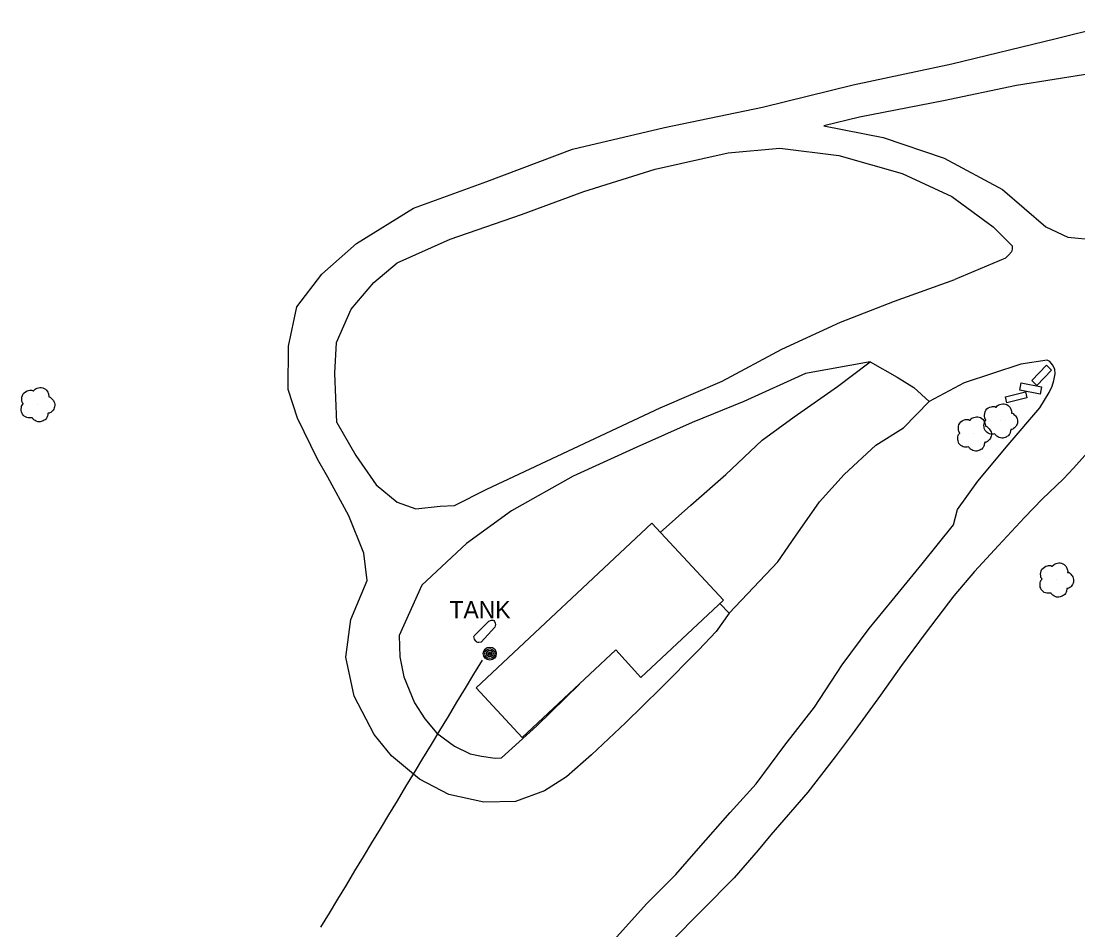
# Model space of a CAD drawing. Extents: x 368532 to 392481, y 10654822 to 10676899.
# Drawn here: x 370919.5 to 371228.1, y 10674746.6 to 10675012 of the extents above; entities that cross this region are included whole.
import ezdxf

# ---------------------------------------------------------------- set-up
doc = ezdxf.new("R2010")
doc.units = 0
for name, color, linetype in [('p_Catenary', 7, 'Continuous'), ('p_road conc barrier', 7, 'Continuous'), ('p_road dirt road', 7, 'Continuous'), ('p_road general road feature', 7, 'Continuous'), ('p_structure building', 7, 'Continuous'), ('p_structure tank', 7, 'Continuous'), ('p_utility general pole', 7, 'Continuous'), ('p_veg tree', 7, 'Continuous')]:
    doc.layers.add(name, color=color, linetype=linetype)

msp = doc.modelspace()

# ---------------------------------------------------------------- linework, layer by layer
at = {"layer": 'p_Catenary'}
msp.add_lwpolyline([(371007.04, 10674747.35), (371009.52, 10674751.46), (371012, 10674755.57), (371014.48, 10674759.67), (371016.96, 10674763.78), (371019.45, 10674767.89), (371021.93, 10674771.99), (371024.41, 10674776.1), (371026.89, 10674780.21), (371029.37, 10674784.31), (371031.86, 10674788.42), (371034.34, 10674792.52), (371036.82, 10674796.63), (371039.3, 10674800.74), (371041.78, 10674804.84), (371044.27, 10674808.95), (371046.75, 10674813.06), (371049.23, 10674817.16), (371051.71, 10674821.27), (371054.19, 10674825.37)], dxfattribs=at)
at = {"layer": 'p_road conc barrier'}
for p, q in [((371214.61, 10674907.02), (371218.96, 10674911.52)), ((371220.45, 10674910.08), (371216.1, 10674905.58)), ((371218.96, 10674911.52), (371220.45, 10674910.08)), ((371216.1, 10674905.58), (371214.61, 10674907.02)), ((371206.92, 10674902.29), (371212.78, 10674903.76)), ((371211.11, 10674904.21), (371211.53, 10674906.37)), ((371217.1, 10674903.05), (371211.11, 10674904.21)), ((371211.53, 10674906.37), (371217.52, 10674905.21)), ((371212.78, 10674903.76), (371213.21, 10674902.04)), ((371217.52, 10674905.21), (371217.1, 10674903.05)), ((371207.36, 10674900.57), (371206.92, 10674902.29)), ((371213.21, 10674902.04), (371207.36, 10674900.57))]:
    msp.add_line(p, q, dxfattribs=at)
at = {"layer": 'p_road dirt road'}
for p, q in [((371221.8, 10675006.97), (371241.96, 10675012.03)), ((371191.34, 10674999.54), (371221.8, 10675006.97)), ((371162.5, 10674993.47), (371191.34, 10674999.54)), ((371232.15, 10674996.7), (371210.22, 10674993.27)), ((371136.01, 10674986.9), (371162.5, 10674993.47)), ((371210.22, 10674993.27), (371188.87, 10674988.75)), ((371107.41, 10674980.93), (371136.01, 10674986.9)), ((371188.87, 10674988.75), (371164.34, 10674983.94)), ((371164.34, 10674983.94), (371153.88, 10674981.48)), ((371080.49, 10674974.59), (371107.41, 10674980.93)), ((371153.88, 10674981.48), (371171.26, 10674978.03)), ((371171.26, 10674978.03), (371189.09, 10674971.99)), ((371055.53, 10674965.22), (371080.49, 10674974.59)), ((371125.94, 10674973.54), (371141.1, 10674974.88)), ((371141.1, 10674974.88), (371158.3, 10674972.81)), ((371104.63, 10674968.75), (371125.94, 10674973.54)), ((371158.3, 10674972.81), (371176.76, 10674967.48)), ((371189.09, 10674971.99), (371206.11, 10674962.82)), ((371083.78, 10674962.31), (371104.63, 10674968.75)), ((371034.06, 10674957.4), (371055.53, 10674965.22)), ((371176.76, 10674967.48), (371191.26, 10674960.78)), ((371065.64, 10674955.56), (371083.78, 10674962.31)), ((371206.11, 10674962.82), (371218.78, 10674951.94)), ((371191.26, 10674960.78), (371203.41, 10674951.94)), ((371017.44, 10674947.07), (371034.06, 10674957.4)), ((371044.73, 10674948.31), (371065.64, 10674955.56)), ((371203.41, 10674951.94), (371208.88, 10674946.36)), ((371218.78, 10674951.94), (371225.14, 10674948.88)), ((371007.32, 10674938.11), (371017.44, 10674947.07)), ((371029.34, 10674941.46), (371044.73, 10674948.31)), ((371225.14, 10674948.88), (371233.23, 10674948.16)), ((371207.93, 10674943.75), (371206.97, 10674942.82)), ((371208.7, 10674944.61), (371207.93, 10674943.75)), ((371208.87, 10674945.39), (371208.7, 10674944.61)), ((371208.88, 10674946.36), (371208.87, 10674945.39)), ((371022.44, 10674935.64), (371029.34, 10674941.46)), ((371206.97, 10674942.82), (371192.15, 10674936.57)), ((370999.95, 10674928.6), (371007.32, 10674938.11)), ((371015.83, 10674927.88), (371022.44, 10674935.64)), ((371174.56, 10674930.22), (371192.15, 10674936.57)), ((370997.51, 10674917.07), (370999.95, 10674928.6)), ((371158.81, 10674924.14), (371174.56, 10674930.22)), ((371011.55, 10674918.2), (371015.83, 10674927.88)), ((371141.61, 10674916.19), (371158.81, 10674924.14)), ((370997.47, 10674904.43), (370997.51, 10674917.07)), ((371011.1, 10674909.21), (371011.55, 10674918.2)), ((371124.22, 10674906.89), (371141.61, 10674916.19)), ((371219.12, 10674912.96), (371211.46, 10674911.84)), ((371219.88, 10674912.56), (371219.12, 10674912.96)), ((371167.48, 10674912.53), (371148.59, 10674909.15)), ((371211.46, 10674911.84), (371194.91, 10674906.39)), ((371220.72, 10674911.65), (371219.88, 10674912.56)), ((371221.35, 10674910.32), (371220.72, 10674911.65)), ((371221.49, 10674909), (371221.35, 10674910.32)), ((371011.69, 10674894.82), (371011.1, 10674909.21)), ((371106.07, 10674899.03), (371124.22, 10674906.89)), ((371148.59, 10674909.15), (371130.52, 10674900.88)), ((371220.56, 10674905.43), (371221.1, 10674907.02)), ((371221.1, 10674907.02), (371221.49, 10674909)), ((371000.15, 10674896.05), (370997.47, 10674904.43)), ((371194.91, 10674906.39), (371184.67, 10674900.97)), ((371216.98, 10674899.08), (371219.76, 10674903.56)), ((371219.76, 10674903.56), (371220.56, 10674905.43)), ((371130.52, 10674900.88), (371115.48, 10674894.82)), ((371055.48, 10674875.3), (371106.07, 10674899.03)), ((371207.7, 10674888.3), (371216.98, 10674899.08)), ((371005.99, 10674884.04), (371000.15, 10674896.05)), ((371011.69, 10674894.82), (371017.2, 10674885.16)), ((371115.48, 10674894.82), (371099.26, 10674887.54)), ((371198.87, 10674877.67), (371207.7, 10674888.3)), ((371017.2, 10674885.16), (371023.19, 10674876.57)), ((371099.26, 10674887.54), (371080.67, 10674879.13)), ((371231.93, 10674887.1), (371226.78, 10674881.49)), ((371009, 10674878.79), (371005.99, 10674884.04)), ((371015.17, 10674867.49), (371009, 10674878.79)), ((371080.67, 10674879.13), (371062.68, 10674868.97)), ((371226.78, 10674881.49), (371223.91, 10674878.34)), ((371023.19, 10674876.57), (371029.31, 10674871.47)), ((371192.94, 10674869.37), (371198.87, 10674877.67)), ((371223.91, 10674878.34), (371217.68, 10674872.38)), ((371046.06, 10674870.54), (371055.48, 10674875.3)), ((371029.31, 10674871.47), (371034.71, 10674869.61)), ((371034.71, 10674869.61), (371041.84, 10674870.32)), ((371041.84, 10674870.32), (371046.06, 10674870.54)), ((371217.68, 10674872.38), (371212.49, 10674867)), ((371019.56, 10674856.58), (371015.17, 10674867.49)), ((371062.68, 10674868.97), (371049.55, 10674859.41)), ((371191.75, 10674864.85), (371192.94, 10674869.37)), ((371212.49, 10674867), (371204.94, 10674858.87)), ((371182.67, 10674853.5), (371191.75, 10674864.85)), ((371049.55, 10674859.41), (371036.52, 10674847.26)), ((371204.94, 10674858.87), (371197.95, 10674851.22)), ((371020.51, 10674848.67), (371019.56, 10674856.58)), ((371173.84, 10674842.75), (371182.67, 10674853.5)), ((371197.95, 10674851.22), (371191.89, 10674844.16)), ((371015.79, 10674837.28), (371020.51, 10674848.67)), ((371036.52, 10674847.26), (371029.87, 10674832.59)), ((371167.11, 10674834.61), (371173.84, 10674842.75)), ((371191.89, 10674844.16), (371183.55, 10674833.12)), ((371126.29, 10674839.14), (371122.44, 10674833.75)), ((371014.35, 10674826.26), (371015.79, 10674837.28)), ((371029.87, 10674832.59), (371030.06, 10674826.3)), ((371122.44, 10674833.75), (371117.29, 10674828.25)), ((371159.24, 10674824.03), (371167.11, 10674834.61)), ((371183.55, 10674833.12), (371176.64, 10674823.76)), ((371016.71, 10674814.84), (371014.35, 10674826.26)), ((371030.06, 10674826.3), (371031.2, 10674820.48)), ((371117.29, 10674828.25), (371106.29, 10674817.19)), ((371151.21, 10674811.68), (371159.24, 10674824.03)), ((371176.64, 10674823.76), (371170.47, 10674815.17)), ((371031.2, 10674820.48), (371034.36, 10674812.94)), ((371070.06, 10674806.14), (371082.5, 10674818.33)), ((371106.29, 10674817.19), (371096.01, 10674807.1)), ((371022.6, 10674803.61), (371016.71, 10674814.84)), ((371170.47, 10674815.17), (371162.17, 10674803.74)), ((371034.36, 10674812.94), (371037.4, 10674808.19)), ((371142.54, 10674800.56), (371151.21, 10674811.68)), ((371037.4, 10674808.19), (371040.9, 10674804.06)), ((371059.72, 10674796.87), (371070.06, 10674806.14)), ((371096.01, 10674807.1), (371086.02, 10674797.71)), ((371027.6, 10674797.43), (371022.6, 10674803.61)), ((371040.9, 10674804.06), (371046.02, 10674800.28)), ((371162.17, 10674803.74), (371157.19, 10674797.16)), ((371046.02, 10674800.28), (371050.64, 10674798.04)), ((371134.15, 10674789.28), (371142.54, 10674800.56)), ((371035.78, 10674790.57), (371027.6, 10674797.43)), ((371050.64, 10674798.04), (371053.9, 10674797.32)), ((371053.9, 10674797.32), (371057.96, 10674796.72)), ((371057.96, 10674796.72), (371059.72, 10674796.87)), ((371086.02, 10674797.71), (371078.78, 10674791.26)), ((371157.19, 10674797.16), (371149.2, 10674786.8)), ((371044.38, 10674786.14), (371035.78, 10674790.57)), ((371078.78, 10674791.26), (371072.31, 10674787.23)), ((371126.55, 10674780.87), (371134.15, 10674789.28)), ((371054.63, 10674783.92), (371044.38, 10674786.14)), ((371072.31, 10674787.23), (371063.89, 10674784.07)), ((371149.2, 10674786.8), (371138.39, 10674774.34)), ((371063.89, 10674784.07), (371054.63, 10674783.92)), ((371117.35, 10674770.32), (371126.55, 10674780.87)), ((371138.39, 10674774.34), (371134.75, 10674769.82)), ((371110.65, 10674762.75), (371117.35, 10674770.32)), ((371134.75, 10674769.82), (371127.76, 10674761.76)), ((371102.19, 10674754.24), (371110.65, 10674762.75)), ((371127.76, 10674761.76), (371118.34, 10674752.35)), ((371093.35, 10674744.45), (371102.19, 10674754.24)), ((371118.34, 10674752.35), (371109, 10674742.9))]:
    msp.add_line(p, q, dxfattribs=at)
at = {"layer": 'p_road general road feature'}
for p, q in [((371157.94, 10674905.33), (371167.05, 10674912.23)), ((371167.05, 10674912.23), (371167.48, 10674912.53)), ((371167.48, 10674912.53), (371175.35, 10674907.99)), ((371175.35, 10674907.99), (371180.16, 10674905.01)), ((371145.29, 10674896.45), (371157.94, 10674905.33)), ((371180.16, 10674905.01), (371184.67, 10674900.97)), ((371177.17, 10674893.21), (371184.67, 10674900.97)), ((371135.91, 10674889.67), (371145.29, 10674896.45)), ((371169.06, 10674888.18), (371177.17, 10674893.21)), ((371125.28, 10674879.64), (371135.91, 10674889.67)), ((371159.84, 10674879.64), (371169.06, 10674888.18)), ((371115.04, 10674870.66), (371125.28, 10674879.64)), ((371152.61, 10674871.57), (371159.84, 10674879.64)), ((371106.15, 10674862.7), (371115.04, 10674870.66)), ((371145.6, 10674861.63), (371152.61, 10674871.57)), ((371140.47, 10674854.07), (371145.6, 10674861.63)), ((371126.29, 10674839.14), (371140.47, 10674854.07)), ((371123.5, 10674841.94), (371126.29, 10674839.14))]:
    msp.add_line(p, q, dxfattribs=at)
at = {"layer": 'p_structure building'}
msp.add_lwpolyline([(371103.67, 10674865.36), (371124.56, 10674842.93), (371100.47, 10674820.3), (371093.2, 10674828.35), (371065.84, 10674802.73), (371052.34, 10674817.25)], close=True, dxfattribs=at)
at = {"layer": 'p_structure tank'}
for p, q in [((371051.8, 10674832.52), (371056.06, 10674836.78)), ((371056.06, 10674836.78), (371056.84, 10674837.05)), ((371056.84, 10674837.05), (371057.22, 10674837.07)), ((371057.22, 10674837.07), (371057.5, 10674836.92)), ((371057.5, 10674836.92), (371057.7, 10674836.66)), ((371057.7, 10674836.66), (371057.94, 10674836.16)), ((371058.05, 10674835.75), (371057.86, 10674834.98)), ((371057.94, 10674836.16), (371058.05, 10674835.75)), ((371051.73, 10674832.23), (371051.8, 10674832.52)), ((371057.86, 10674834.98), (371053.79, 10674830.67)), ((371051.74, 10674831.92), (371051.73, 10674832.23)), ((371051.91, 10674831.54), (371051.74, 10674831.92)), ((371052.07, 10674831.19), (371051.91, 10674831.54)), ((371052.24, 10674830.96), (371052.07, 10674831.19)), ((371052.42, 10674830.79), (371052.24, 10674830.96)), ((371052.58, 10674830.67), (371052.42, 10674830.79)), ((371052.86, 10674830.57), (371052.58, 10674830.67)), ((371053.17, 10674830.53), (371052.86, 10674830.57)), ((371053.79, 10674830.67), (371053.17, 10674830.53))]:
    msp.add_line(p, q, dxfattribs=at)
at = {"layer": 'p_utility general pole'}
for radius in [1.9, 1.44, 0.973, 0.539, 0.192]:
    msp.add_circle((371056.35, 10674827.3), radius, dxfattribs=at)
at = {"layer": 'p_veg tree'}
for p, q in [((370924.19, 10674900.07), (370924.19, 10674900.07)), ((371205.38, 10674895.3), (371205.38, 10674895.3)), ((371197.74, 10674891.52), (371197.74, 10674891.52)), ((371221.76, 10674848.85), (371221.76, 10674848.85))]:
    msp.add_line(p, q, dxfattribs=at)
for points in [[(370922.65, 10674896.2), (370921.1, 10674896.24), (370919.83, 10674897.24), (370919.49, 10674898.7), (370919.62, 10674899.55), (370919.98, 10674900.15), (370920.08, 10674900.26), (370920.02, 10674900.35), (370919.67, 10674901.24), (370920.05, 10674903.13), (370921.66, 10674904.17), (370922.95, 10674904.06), (370923.09, 10674904.01), (370923.17, 10674904.11), (370924.15, 10674904.82), (370925.77, 10674904.91), (370927.11, 10674903.91), (370927.51, 10674902.9), (370927.56, 10674902.35), (370927.54, 10674902.24), (370927.64, 10674902.24), (370928.23, 10674901.93), (370929.05, 10674900.94), (370929.25, 10674899.38), (370928.59, 10674898.15), (370927.62, 10674897.55), (370927.36, 10674897.5), (370927.31, 10674897.45), (370927.3, 10674897.39), (370927.23, 10674896.94), (370926.88, 10674896.03), (370925.93, 10674895.28), (370924.7, 10674894.98), (370923.21, 10674895.57), (370922.63, 10674896.21)], [(371203.84, 10674891.43), (371202.29, 10674891.47), (371201.03, 10674892.48), (371200.68, 10674893.94), (371200.81, 10674894.78), (371201.17, 10674895.39), (371201.27, 10674895.49), (371201.21, 10674895.59), (371200.86, 10674896.48), (371201.24, 10674898.37), (371202.85, 10674899.41), (371204.14, 10674899.3), (371204.28, 10674899.25), (371204.36, 10674899.35), (371205.35, 10674900.06), (371206.96, 10674900.15), (371208.3, 10674899.15), (371208.7, 10674898.14), (371208.75, 10674897.59), (371208.73, 10674897.48), (371208.83, 10674897.48), (371209.43, 10674897.16), (371210.24, 10674896.18), (371210.44, 10674894.62), (371209.78, 10674893.39), (371208.81, 10674892.79), (371208.55, 10674892.73), (371208.5, 10674892.69), (371208.49, 10674892.62), (371208.42, 10674892.17), (371208.07, 10674891.27), (371207.12, 10674890.52), (371205.89, 10674890.22), (371204.4, 10674890.8), (371203.82, 10674891.44)], [(371196.2, 10674887.65), (371194.65, 10674887.69), (371193.38, 10674888.69), (371193.03, 10674890.15), (371193.16, 10674890.99), (371193.52, 10674891.6), (371193.63, 10674891.71), (371193.57, 10674891.8), (371193.21, 10674892.69), (371193.6, 10674894.58), (371195.2, 10674895.62), (371196.5, 10674895.51), (371196.64, 10674895.46), (371196.71, 10674895.56), (371197.7, 10674896.27), (371199.31, 10674896.36), (371200.66, 10674895.36), (371201.05, 10674894.35), (371201.1, 10674893.8), (371201.08, 10674893.69), (371201.19, 10674893.69), (371201.78, 10674893.37), (371202.6, 10674892.39), (371202.79, 10674890.83), (371202.13, 10674889.6), (371201.17, 10674889), (371200.91, 10674888.95), (371200.86, 10674888.9), (371200.85, 10674888.84), (371200.78, 10674888.39), (371200.43, 10674887.48), (371199.47, 10674886.73), (371198.25, 10674886.43), (371196.76, 10674887.01), (371196.18, 10674887.65)], [(371220.23, 10674844.98), (371218.67, 10674845.02), (371217.41, 10674846.02), (371217.06, 10674847.48), (371217.19, 10674848.33), (371217.55, 10674848.93), (371217.65, 10674849.04), (371217.59, 10674849.13), (371217.24, 10674850.02), (371217.62, 10674851.91), (371219.23, 10674852.96), (371220.53, 10674852.84), (371220.66, 10674852.79), (371220.74, 10674852.89), (371221.73, 10674853.6), (371223.34, 10674853.69), (371224.68, 10674852.69), (371225.08, 10674851.68), (371225.13, 10674851.13), (371225.11, 10674851.02), (371225.22, 10674851.02), (371225.81, 10674850.71), (371226.63, 10674849.72), (371226.82, 10674848.16), (371226.16, 10674846.93), (371225.19, 10674846.34), (371224.93, 10674846.28), (371224.88, 10674846.23), (371224.87, 10674846.17), (371224.81, 10674845.72), (371224.45, 10674844.81), (371223.5, 10674844.06), (371222.27, 10674843.76), (371220.78, 10674844.35), (371220.21, 10674844.99)]]:
    msp.add_spline(points, degree=3, dxfattribs=at)

# ---------------------------------------------------------------- texts
at = {"layer": 'p_structure tank'}
msp.add_text(' TANK', height=5, dxfattribs=at).set_placement((371042.72, 10674837.62))

doc.saveas('drawing.dxf')
